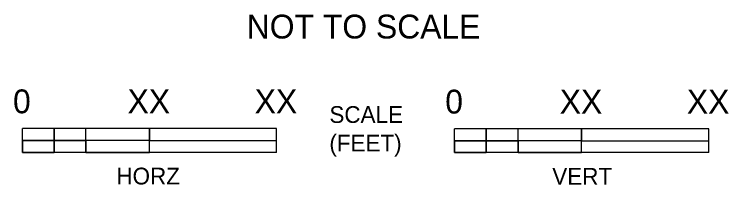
# Model space of a CAD drawing. Extents: x 1.86 to 2.73, y -0.19 to 1.72.
import ezdxf

# ---------------------------------------------------------------- set-up
doc = ezdxf.new("R2010")
doc.units = 0
doc.layers.add('ANNO-SHT', color=7, linetype='Continuous')
doc.layers.add('ANNO-SYMB', color=7, linetype='Continuous')

msp = doc.modelspace()

# ---------------------------------------------------------------- linework, layer by layer
at = {"layer": 'ANNO-SYMB'}
for p, q in [((2.03314, -0.15495), (1.86648, -0.15495)), ((1.86648, -0.17058), (1.86648, -0.15495)), ((1.88731, -0.17058), (1.88731, -0.15495)), ((1.90815, -0.17058), (1.90815, -0.15495)), ((1.94981, -0.17058), (1.94981, -0.15512)), ((2.03314, -0.17058), (2.03314, -0.15495)), ((2.31648, -0.15512), (2.14981, -0.15512)), ((2.14981, -0.17074), (2.14981, -0.15512)), ((2.17065, -0.17074), (2.17065, -0.15512)), ((2.19148, -0.17074), (2.19148, -0.15512)), ((2.23315, -0.17074), (2.23315, -0.15528)), ((2.31648, -0.17074), (2.31648, -0.15512)), ((1.90815, -0.16276), (1.86648, -0.16276)), ((2.19148, -0.16293), (2.14981, -0.16293)), ((2.03314, -0.17058), (1.86648, -0.17058)), ((2.31648, -0.17074), (2.14981, -0.17074))]:
    msp.add_line(p, q, dxfattribs=at)
for points in [[(1.90815, -0.15495), (1.88731, -0.15495), (1.88731, -0.16276), (1.90815, -0.16276)], [(1.94981, -0.16285), (2.03314, -0.16285), (2.03314, -0.15495), (1.94981, -0.15495)], [(2.19148, -0.15512), (2.17065, -0.15512), (2.17065, -0.16293), (2.19148, -0.16293)], [(2.23315, -0.16301), (2.31648, -0.16301), (2.31648, -0.15512), (2.23315, -0.15512)], [(1.88731, -0.16276), (1.86648, -0.16276), (1.86648, -0.17058), (1.88731, -0.17058)], [(1.86648, -0.16276), (1.88731, -0.16276), (1.88731, -0.17058), (1.86648, -0.17058)], [(1.90815, -0.16276), (1.90815, -0.17058), (1.94981, -0.17058), (1.94981, -0.16276)], [(2.17065, -0.16293), (2.14981, -0.16293), (2.14981, -0.17074), (2.17065, -0.17074)], [(2.14981, -0.16293), (2.17065, -0.16293), (2.17065, -0.17074), (2.14981, -0.17074)], [(2.19148, -0.16293), (2.19148, -0.17074), (2.23315, -0.17074), (2.23315, -0.16293)]]:
    msp.add_lwpolyline(points, close=True, dxfattribs=at)

# ---------------------------------------------------------------- texts
at = {"layer": 'ANNO-SHT'}
for s, height, p in [('NOT TO SCALE', 0.015625, (2.01357, -0.09596)), ('SCALE', 0.011, (2.06777, -0.15127)), ('(FEET)', 0.011, (2.06776, -0.16997)), ('HORZ', 0.011, (1.92812, -0.19158)), ('VERT', 0.011, (2.2139, -0.19174))]:
    msp.add_text(s, height=height, dxfattribs=at).set_placement(p)
at = {"layer": 'ANNO-SYMB'}
for s, height, p in [('0', 0.01562, (1.86037, -0.14495)), ('XX', 0.015625, (1.93546, -0.14495)), ('XX', 0.015625, (2.01879, -0.14495)), ('0', 0.01562, (2.14371, -0.14512)), ('XX', 0.015625, (2.21879, -0.14512)), ('XX', 0.015625, (2.30213, -0.14512))]:
    msp.add_text(s, height=height, dxfattribs=at).set_placement(p)

doc.saveas('drawing.dxf')
